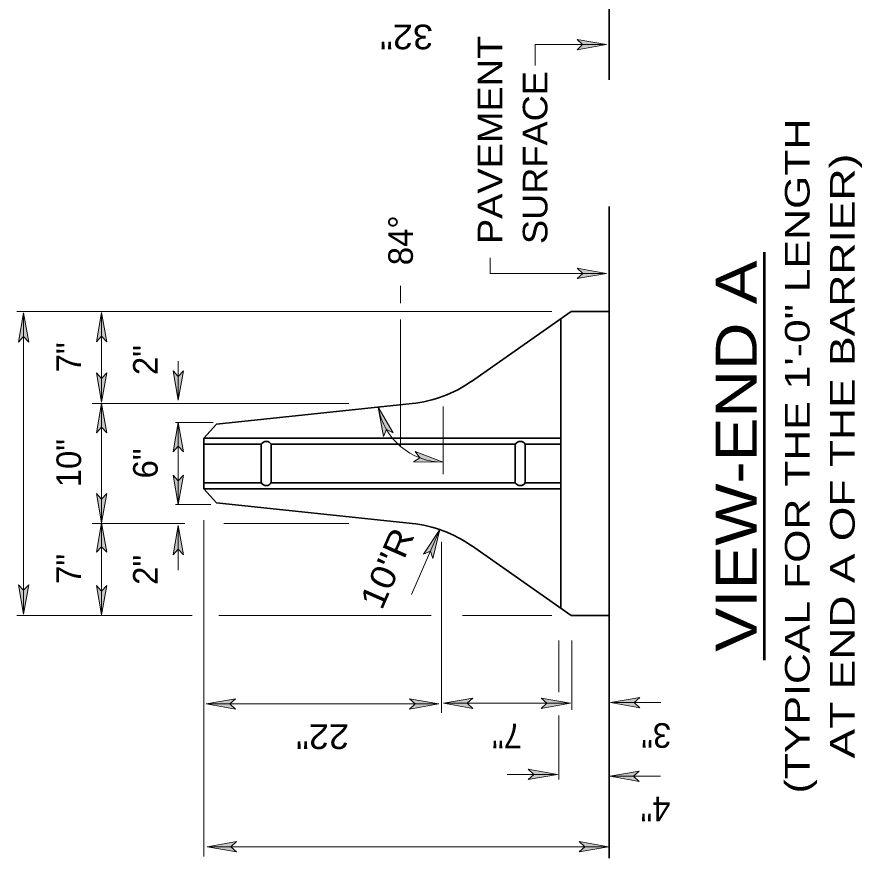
# Model space of a CAD drawing. Extents: x 12.6 to 19.4, y 6.1 to 16.3.
# Drawn here: x 17.215 to 19.276, y 8.125 to 10.176 of the extents above; entities that cross this region are included whole.
import ezdxf
from ezdxf.enums import TextEntityAlignment as Align

# ---------------------------------------------------------------- set-up
doc = ezdxf.new("R2010")
doc.units = 0
doc.header["$LTSCALE"] = 0.024
for name, color, linetype, lineweight in [('1', 7, 'Continuous', 35), ('10', 7, 'Continuous', 13), ('12', 7, 'Continuous', 53)]:
    doc.layers.add(name, color=color, linetype=linetype, lineweight=lineweight)

msp = doc.modelspace()

# ---------------------------------------------------------------- hatches: boundary and pattern name
at = {"layer": '10'}
for points in [[(18.5807, 10.1209), (18.6522, 10.1083), (18.5807, 10.0957), (18.5942, 10.1083)], [(18.5811, 9.5633), (18.6526, 9.5507), (18.5811, 9.5381), (18.5946, 9.5507)], [(17.2184, 9.3832), (17.231, 9.4547), (17.2436, 9.3832), (17.231, 9.3967)], [(17.4085, 9.384), (17.4211, 9.4555), (17.4337, 9.384), (17.4211, 9.3975)], [(17.4337, 9.3081), (17.4211, 9.2366), (17.4085, 9.3081), (17.4211, 9.2946)], [(17.6206, 9.3131), (17.608, 9.2416), (17.5954, 9.3131), (17.608, 9.2996)], [(17.4085, 9.1622), (17.4211, 9.2337), (17.4337, 9.1622), (17.4211, 9.1757)], [(18.1084, 9.1533), (18.0957, 9.2248), (18.1321, 9.162), (18.1156, 9.1703)], [(17.5954, 9.1158), (17.608, 9.1873), (17.6206, 9.1158), (17.608, 9.1293)], [(18.1861, 9.1161), (18.2541, 9.0906), (18.1816, 9.0911), (18.1971, 9.1011)], [(17.6206, 9.0588), (17.608, 8.9873), (17.5954, 9.0588), (17.608, 9.0453)], [(17.4337, 9.0137), (17.4211, 8.9422), (17.4085, 9.0137), (17.4211, 9.0002)], [(17.4085, 8.8707), (17.4211, 8.9422), (17.4337, 8.8707), (17.4211, 8.8842)], [(17.5954, 8.8645), (17.608, 8.936), (17.6206, 8.8645), (17.608, 8.878)], [(18.2061, 8.866), (18.2464, 8.9264), (18.2292, 8.8559), (18.2231, 8.8733)], [(17.2436, 8.7916), (17.231, 8.7201), (17.2184, 8.7916), (17.231, 8.7781)], [(17.4337, 8.7899), (17.4211, 8.7184), (17.4085, 8.7899), (17.4211, 8.7764)], [(17.7475, 8.4887), (17.676, 8.5013), (17.7475, 8.5139), (17.734, 8.5013)], [(18.1723, 8.5139), (18.2438, 8.5013), (18.1723, 8.4887), (18.1858, 8.5013)], [(18.3263, 8.4903), (18.2548, 8.5029), (18.3263, 8.5155), (18.3128, 8.5029)], [(18.4935, 8.5155), (18.565, 8.5029), (18.4935, 8.4903), (18.507, 8.5029)], [(18.7337, 8.4917), (18.6622, 8.5043), (18.7337, 8.5169), (18.7202, 8.5043)], [(18.4617, 8.3419), (18.5332, 8.3293), (18.4617, 8.3167), (18.4752, 8.3293)], [(18.7322, 8.3122), (18.6607, 8.3248), (18.7322, 8.3374), (18.7187, 8.3248)], [(17.7501, 8.1405), (17.6786, 8.1531), (17.7501, 8.1657), (17.7366, 8.1531)], [(18.5859, 8.1657), (18.6574, 8.1531), (18.5859, 8.1405), (18.5994, 8.1531)]]:
    msp.add_hatch(color=256, dxfattribs=at).paths.add_polyline_path(points)

# ---------------------------------------------------------------- linework, layer by layer
at = {"layer": '1'}
for p, q in [((18.6593, 10.0229), (18.6593, 11.7975)), ((18.6593, 8.1253), (18.6593, 9.7137)), ((18.5413, 8.7354), (18.5413, 9.4402)), ((18.1782, 9.2335), (17.7012, 9.1832)), ((17.6703, 9.1491), (17.7012, 9.1832)), ((17.6703, 9.0255), (17.6703, 9.1491)), ((17.6703, 9.1491), (18.5413, 9.1491)), ((17.6703, 9.1346), (17.8105, 9.1346)), ((17.8105, 9.0405), (17.8105, 9.1339)), ((17.8347, 9.1346), (18.43, 9.1346)), ((17.8347, 9.0405), (17.8347, 9.1339)), ((18.43, 9.0404), (18.43, 9.1339)), ((18.5413, 9.1346), (18.4542, 9.1346)), ((18.4542, 9.0404), (18.4542, 9.1339)), ((17.6703, 9.0405), (17.8105, 9.0405)), ((17.8347, 9.0405), (18.43, 9.0405)), ((18.5413, 9.0405), (18.4542, 9.0405)), ((17.6703, 9.0255), (17.7012, 8.9913)), ((17.6703, 9.0255), (18.5413, 9.0255)), ((18.1782, 8.9412), (17.7012, 8.9913))]:
    msp.add_line(p, q, dxfattribs=at)
for points in [[(18.6593, 9.4581), (18.5667, 9.4581), (18.3231, 9.2875)], [(18.6593, 8.7163), (18.5667, 8.7163), (18.3231, 8.887)]]:
    msp.add_lwpolyline(points, dxfattribs=at)
for centre, radius, start, end in [((18.1458, 9.5407), 0.309, 276.0131, 304.9919), ((17.8227, 9.1272), 0.0139, 29.1598, 150.8402), ((18.4422, 9.1271), 0.0139, 29.1598, 150.8402), ((17.8227, 9.0473), 0.0139, 209.1598, 330.8402), ((18.4422, 9.0472), 0.0139, 209.1598, 330.8402), ((18.1458, 8.6337), 0.309, 55.008, 83.9868)]:
    msp.add_arc(centre, radius, start, end, dxfattribs=at)
at = {"layer": '10'}
for p, q in [((18.6522, 10.1083), (18.5807, 10.1209)), ((18.4784, 10.1083), (18.6522, 10.1083)), ((18.4784, 10.0574), (18.4784, 10.1083)), ((18.6522, 10.1083), (18.5807, 10.0957)), ((18.6526, 9.5507), (18.5811, 9.5633)), ((18.6526, 9.5507), (18.5811, 9.5381)), ((18.1503, 9.4781), (18.1503, 9.5207)), ((18.5191, 9.4581), (17.2147, 9.4581)), ((17.231, 9.4547), (17.2184, 9.3832)), ((17.231, 8.7201), (17.231, 9.4547)), ((17.231, 9.4547), (17.2436, 9.3832)), ((17.4211, 9.4555), (17.4085, 9.384)), ((17.4211, 9.2366), (17.4211, 9.4555)), ((17.4211, 9.4555), (17.4337, 9.384)), ((18.1503, 9.1287), (18.1503, 9.4381)), ((17.608, 9.2416), (17.608, 9.337)), ((17.4211, 9.2366), (17.4085, 9.3081)), ((17.4211, 9.2366), (17.4337, 9.3081)), ((17.608, 9.2416), (17.5954, 9.3131)), ((17.608, 9.2416), (17.6206, 9.3131)), ((17.4211, 9.2337), (17.4085, 9.1622)), ((17.4211, 9.2337), (17.4337, 9.1622)), ((18.0242, 9.2335), (17.3982, 9.2335)), ((18.0957, 9.2248), (18.1084, 9.1533)), ((18.0957, 9.2248), (18.1321, 9.162)), ((18.2541, 9.2262), (18.2541, 9.0612)), ((17.608, 9.1873), (17.5954, 9.1158)), ((17.6929, 9.1873), (17.6012, 9.1873)), ((17.608, 8.9873), (17.608, 9.1873)), ((17.608, 9.1873), (17.6206, 9.1158)), ((18.2541, 9.0906), (18.1861, 9.1161)), ((18.2541, 9.0906), (18.1816, 9.0911)), ((17.608, 8.9873), (17.5954, 9.0588)), ((17.608, 8.9873), (17.6206, 9.0588)), ((17.4211, 8.9422), (17.4085, 9.0137)), ((17.4211, 8.9422), (17.4337, 9.0137)), ((17.6878, 8.9873), (17.6012, 8.9873)), ((17.6702, 8.9491), (17.6702, 8.1291)), ((17.6243, 8.9412), (17.3982, 8.9412)), ((17.4211, 8.9422), (17.4085, 8.8707)), ((17.4211, 8.9422), (17.4337, 8.8707)), ((17.608, 8.936), (17.5954, 8.8645)), ((17.608, 8.827), (17.608, 8.936)), ((17.608, 8.936), (17.6206, 8.8645)), ((17.7194, 8.9412), (18.0242, 8.9412)), ((18.2464, 8.9264), (18.1769, 8.7679)), ((18.2464, 8.9264), (18.2061, 8.866)), ((18.2464, 8.9264), (18.2292, 8.8559)), ((18.2504, 8.4791), (18.2504, 8.896)), ((17.231, 8.7201), (17.2184, 8.7916)), ((17.231, 8.7201), (17.2436, 8.7916)), ((17.4211, 8.7184), (17.4085, 8.7899)), ((17.4211, 8.7184), (17.4337, 8.7899)), ((17.2147, 8.7163), (17.6424, 8.7163)), ((17.7068, 8.7163), (18.2251, 8.7163)), ((18.5191, 8.7163), (18.3012, 8.7163)), ((18.5362, 8.6559), (18.5362, 8.5295)), ((18.5683, 8.6559), (18.5683, 8.4864)), ((17.676, 8.5013), (17.7475, 8.5139)), ((18.2438, 8.5013), (18.1723, 8.5139)), ((18.2548, 8.5029), (18.3263, 8.5155)), ((18.565, 8.5029), (18.4935, 8.5155)), ((18.6622, 8.5043), (18.7337, 8.5169)), ((18.2438, 8.5013), (17.676, 8.5013)), ((17.676, 8.5013), (17.7475, 8.4887)), ((18.2438, 8.5013), (18.1723, 8.4887)), ((18.565, 8.5029), (18.2548, 8.5029)), ((18.2548, 8.5029), (18.3263, 8.4903)), ((18.565, 8.5029), (18.4935, 8.4903)), ((18.7853, 8.5043), (18.6622, 8.5043)), ((18.6622, 8.5043), (18.7337, 8.4917)), ((18.5362, 8.317), (18.5362, 8.4729)), ((18.5332, 8.3293), (18.4102, 8.3293)), ((18.5332, 8.3293), (18.4617, 8.3419)), ((18.5332, 8.3293), (18.4617, 8.3167)), ((18.6607, 8.3248), (18.7322, 8.3374)), ((18.7838, 8.3248), (18.6607, 8.3248)), ((18.6607, 8.3248), (18.7322, 8.3122)), ((17.6786, 8.1531), (17.7501, 8.1657)), ((18.6574, 8.1531), (18.5859, 8.1657)), ((18.6574, 8.1531), (17.6786, 8.1531)), ((17.6786, 8.1531), (17.7501, 8.1405)), ((18.6574, 8.1531), (18.5859, 8.1405))]:
    msp.add_line(p, q, dxfattribs=at)
for points in [[(18.5807, 10.1209), (18.5942, 10.1083), (18.5807, 10.0957)], [(18.3684, 9.5887), (18.3684, 9.5507), (18.6526, 9.5507)], [(18.5811, 9.5633), (18.5946, 9.5507), (18.5811, 9.5381)], [(17.2184, 9.3832), (17.231, 9.3967), (17.2436, 9.3832)], [(17.4085, 9.384), (17.4211, 9.3975), (17.4337, 9.384)], [(17.4337, 9.3081), (17.4211, 9.2946), (17.4085, 9.3081)], [(17.6206, 9.3131), (17.608, 9.2996), (17.5954, 9.3131)], [(17.4211, 8.7184), (17.4211, 8.9422), (17.4211, 9.2337)], [(17.4085, 9.1622), (17.4211, 9.1757), (17.4337, 9.1622)], [(18.1084, 9.1533), (18.1156, 9.1703), (18.1321, 9.162)], [(17.5954, 9.1158), (17.608, 9.1293), (17.6206, 9.1158)], [(18.1861, 9.1161), (18.1971, 9.1011), (18.1816, 9.0911)], [(17.6206, 9.0588), (17.608, 9.0453), (17.5954, 9.0588)], [(17.4337, 9.0137), (17.4211, 9.0002), (17.4085, 9.0137)], [(17.4085, 8.8707), (17.4211, 8.8842), (17.4337, 8.8707)], [(17.5954, 8.8645), (17.608, 8.878), (17.6206, 8.8645)], [(18.2061, 8.866), (18.2231, 8.8733), (18.2292, 8.8559)], [(17.2436, 8.7916), (17.231, 8.7781), (17.2184, 8.7916)], [(17.4337, 8.7899), (17.4211, 8.7764), (17.4085, 8.7899)], [(17.7475, 8.4887), (17.734, 8.5013), (17.7475, 8.5139)], [(18.1723, 8.5139), (18.1858, 8.5013), (18.1723, 8.4887)], [(18.3263, 8.4903), (18.3128, 8.5029), (18.3263, 8.5155)], [(18.4935, 8.5155), (18.507, 8.5029), (18.4935, 8.4903)], [(18.7337, 8.4917), (18.7202, 8.5043), (18.7337, 8.5169)], [(18.4617, 8.3419), (18.4752, 8.3293), (18.4617, 8.3167)], [(18.7322, 8.3122), (18.7187, 8.3248), (18.7322, 8.3374)], [(17.7501, 8.1405), (17.7366, 8.1531), (17.7501, 8.1657)], [(18.5859, 8.1657), (18.5994, 8.1531), (18.5859, 8.1405)]]:
    msp.add_lwpolyline(points, dxfattribs=at)
for points in [[(18.5807, 10.1209), (18.6522, 10.1083), (18.5807, 10.0957), (18.5942, 10.1083)], [(18.5811, 9.5633), (18.6526, 9.5507), (18.5811, 9.5381), (18.5946, 9.5507)], [(17.2184, 9.3832), (17.231, 9.4547), (17.2436, 9.3832), (17.231, 9.3967)], [(17.4085, 9.384), (17.4211, 9.4555), (17.4337, 9.384), (17.4211, 9.3975)], [(17.4337, 9.3081), (17.4211, 9.2366), (17.4085, 9.3081), (17.4211, 9.2946)], [(17.6206, 9.3131), (17.608, 9.2416), (17.5954, 9.3131), (17.608, 9.2996)], [(17.4085, 9.1622), (17.4211, 9.2337), (17.4337, 9.1622), (17.4211, 9.1757)], [(18.1084, 9.1533), (18.0957, 9.2248), (18.1321, 9.162), (18.1156, 9.1703)], [(17.5954, 9.1158), (17.608, 9.1873), (17.6206, 9.1158), (17.608, 9.1293)], [(18.1861, 9.1161), (18.2541, 9.0906), (18.1816, 9.0911), (18.1971, 9.1011)], [(17.6206, 9.0588), (17.608, 8.9873), (17.5954, 9.0588), (17.608, 9.0453)], [(17.4337, 9.0137), (17.4211, 8.9422), (17.4085, 9.0137), (17.4211, 9.0002)], [(17.4085, 8.8707), (17.4211, 8.9422), (17.4337, 8.8707), (17.4211, 8.8842)], [(17.5954, 8.8645), (17.608, 8.936), (17.6206, 8.8645), (17.608, 8.878)], [(18.2061, 8.866), (18.2464, 8.9264), (18.2292, 8.8559), (18.2231, 8.8733)], [(17.2436, 8.7916), (17.231, 8.7201), (17.2184, 8.7916), (17.231, 8.7781)], [(17.4337, 8.7899), (17.4211, 8.7184), (17.4085, 8.7899), (17.4211, 8.7764)], [(17.7475, 8.4887), (17.676, 8.5013), (17.7475, 8.5139), (17.734, 8.5013)], [(18.1723, 8.5139), (18.2438, 8.5013), (18.1723, 8.4887), (18.1858, 8.5013)], [(18.3263, 8.4903), (18.2548, 8.5029), (18.3263, 8.5155), (18.3128, 8.5029)], [(18.4935, 8.5155), (18.565, 8.5029), (18.4935, 8.4903), (18.507, 8.5029)], [(18.7337, 8.4917), (18.6622, 8.5043), (18.7337, 8.5169), (18.7202, 8.5043)], [(18.4617, 8.3419), (18.5332, 8.3293), (18.4617, 8.3167), (18.4752, 8.3293)], [(18.7322, 8.3122), (18.6607, 8.3248), (18.7322, 8.3374), (18.7187, 8.3248)], [(17.7501, 8.1405), (17.6786, 8.1531), (17.7501, 8.1657), (17.7366, 8.1531)], [(18.5859, 8.1657), (18.6574, 8.1531), (18.5859, 8.1405), (18.5994, 8.1531)]]:
    msp.add_lwpolyline(points, close=True, dxfattribs=at)
msp.add_arc((18.2541, 9.2512), 0.1606, 189.4625, 270, dxfattribs=at)
at = {"layer": '12'}
msp.add_line((19.0377, 8.6081), (19.0377, 9.6027), dxfattribs=at)

# ---------------------------------------------------------------- texts
for s, height, rotation, width, p in [('32"', 0.06, 180, 1.1, (18.1647, 10.1571)), ('(TYPICAL FOR THE 1\'-0" LENGTH', 0.06, 90, 1.3, (19.1477, 9.1054)), ('AT END A OF THE BARRIER)', 0.06, 90, 1.35, (19.2577, 9.1054)), ('VIEW-END A', 0.1, 90, 1.2, (19.0189, 9.1054)), ('10"R', 0.06, 66.351, 1.15, (18.145, 8.8199)), ('22"', 0.06, 180, 1.1, (17.9599, 8.4512))]:
    msp.add_text(s, height=height, rotation=rotation, dxfattribs=dict(at, width=width)).set_placement(p, align=Align.CENTER)
for s, width, p in [('PAVEMENT', 1.15, (18.3984, 9.6222)), ('SURFACE', 1.1, (18.5084, 9.6222))]:
    msp.add_text(s, height=0.06, rotation=90, dxfattribs=dict(at, width=width)).set_placement(p)
msp.add_text('84°', height=0.06, rotation=90, dxfattribs=at).set_placement((18.1803, 9.5706))
for s, rotation, p in [('7"', 90, (17.3711, 9.346)), ('2"', 90, (17.558, 9.3393)), ('10"', 90, (17.3711, 9.088)), ('6"', 90, (17.558, 9.0874)), ('7"', 90, (17.3711, 8.8303)), ('2"', 90, (17.558, 8.828)), ('7"', 180, (18.4098, 8.4528)), ('3"', 180, (18.7737, 8.4542)), ('4"', 180, (18.7721, 8.2747))]:
    msp.add_text(s, height=0.06, rotation=rotation, dxfattribs=at).set_placement(p, align=Align.CENTER)

doc.saveas('drawing.dxf')
